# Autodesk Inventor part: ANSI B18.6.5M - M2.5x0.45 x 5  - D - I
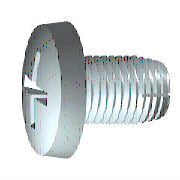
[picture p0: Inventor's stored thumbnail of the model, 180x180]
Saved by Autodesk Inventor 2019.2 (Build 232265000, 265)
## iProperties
IsCustomPart: 1
Created: 2018-01
Part Number: ANSI B18.6.5M - M2.5x0.45 x 5  - D - I
Material: Steel, Mild
Description: Cross Recessed Pan Head Tapping Screw - Type D - Type I - Metric
Document SubType Name: Modeling
Standard: ANSI B18.6.5M
Designer: richard.girt
Standard Revision: 2000 (R2010)
Standards Organization: ANSI
Language: en-US
Size Designation: M2.5x0.45 x 5
Categories: <MemberInstance><Categories><Category DisplayName="Fasteners" InternalName="e4da775c-781d-43d5-af7c-5136215cf5a6" Mnemonic="FSTN"><Category DisplayName="Bolts"
Mass: 0.411512 g
Surface Area: 1.02421 cm^2
Volume: 0.0524219 cm^3
Density: 7.85 g/cm^3
Appearance: Semi-Polished
Author: richard.girt
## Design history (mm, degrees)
revolve "Body" stored, may be unused: angle "d18" = 90 deg
node "IDS_WORKPLANE{1}"
sketch "Sketch2"
  geometry: L1 (-3.339, 0)-(3.339, 0) reference; L2 (0, -3.339)-(0, 3.339) reference; L3 (0, 1.34)-(0, 0); L4 (0, 0)-(1.34, 0); L5 (0, 0)-(1.687, 1.687); L6 (0.35, 1.293)-(0.219, 0.633); L7 (1.293, 0.35)-(0.633, 0.219); L8 (0.35, -1.293)-(0.219, -0.633); L9 (1.293, -0.35)-(0.633, -0.219); L10 (-0.35, 1.293)-(-0.219, 0.633); L11 (-1.293, 0.35)-(-0.633, 0.219); L12 (-1.293, -0.35)-(-0.633, -0.219); L13 (-0.35, -1.293)-(-0.219, -0.633); A1 r 0.447 centre (0, 0) between (0.447, 0) and (0, 0.447); A2 r 1.34 centre (0, 0) between (1.34, 0) and (1.293, 0.35); A3 r 1.34 centre (0, 0) between (0.35, 1.293) and (0, 1.34); A4 r 1.34 centre (0, 0) between (1.293, 0.35) and (0.35, 1.293); A5 r 1.34 centre (0, 0) between (0, -1.34) and (0.35, -1.293); A6 r 1.34 centre (0, 0) between (0.35, -1.293) and (1.293, -0.35); A7 r 1.34 centre (0, 0) between (1.293, -0.35) and (1.34, 0); A8 r 1.34 centre (0, 0) between (-1.293, 0.35) and (-1.34, 0); A9 r 1.34 centre (0, 0) between (-0.35, 1.293) and (-1.293, 0.35); A10 r 1.34 centre (0, 0) between (0, 1.34) and (-0.35, 1.293); A11 r 1.34 centre (0, 0) between (-1.34, 0) and (-1.293, -0.35); A12 r 1.34 centre (0, 0) between (-1.293, -0.35) and (-0.35, -1.293); A13 r 1.34 centre (0, 0) between (-0.35, -1.293) and (0, -1.34); A14 r 0.67 centre (0, 0) between (0.67, 0) and (0, 0.67); A15 r 0.352 centre (0.565, 0.565) between (0.219, 0.633) and (0.633, 0.219); A16 r 0.352 centre (0.565, -0.565) between (0.633, -0.219) and (0.219, -0.633); A17 r 0.352 centre (-0.565, 0.565) between (-0.633, 0.219) and (-0.219, 0.633); A18 r 0.352 centre (-0.565, -0.565) between (-0.219, -0.633) and (-0.633, -0.219); 1 further point
  constraints: 38 point on circle, 22 end point, 19 symmetric about line, 18 centre point, 4 coincident, 3 collinear, 3 tangent, 2 point on line, 1 midpoint, 1 perpendicular, 21 other
  dimensions: "d4" = 45 deg angle of L5 L4; "d5" = 0.89333 diameter of A1 (= 0.333333 x SDM); "d6" = 2.68 diameter of A4 (= SDM); "d7" = 0.35 distance from line of L6.start L3 (= 0.5 x SBR); "d14" = 1.34 diameter of A14 (= 0.5 x SDM)
extrude "Slot" join sketch "Sketch2" taper "d15" = 5 deg; stored distance "d54" = 10
revolve "Cut" stored, may be unused: angle "d56" = 90 deg
workplane "Work Plane3"
body "Solid1"
sketch "Sketch1"
  geometry: L1 (5, 0)-(5, 1.25); L2 (5, 1.25)-(0, 1.25); L3 (3.962, 5.08)-(3.962, 5.08); L4 (-2.1, 0)-(-2.1, 2.316); L5 (-1.902, 1.242)-(-0.988, 0.785); L6 (-0.988, 0.785)-(-0.57, 0); L7 (-0.57, 0)-(5, 0); L8 (-3.751, 0)-(6.458, 0) reference; L9 (0, -1.016)-(0, 6.096) reference; L10 (-1.902, 1.242)-(-2.1, 1.34); L11 (-1.311, 2.385)-(-2.1, 2.316); L12 (-1.311, 2.385)-(0, 2.5); L13 (0, 2.5)-(0, 1.25); A1 r 4 centre (1.9, 0) between (-1.311, 2.385) and (-2.1, 0)
  constraints: 22 end point, 4 collinear, 4 point on circle, 3 point on line, 2 parallel, 1 centre point, 1 horizontal, 1 perpendicular, 1 tangent
  dimensions: "d1" = 2.5 diameter of L2 L7 (= NND); "d2" = 1.53 distance from line of L6.end L4 (= STI); "d11" = 2.68 diameter of L10.end L7 (= SDM); "d12" = 62 deg angle of L6 L7; "d13" = 26.5 deg angle of L5 L7; "d17" = 5 diameter of L12.end L7 (= KOD); "d19" = 5 deg angle of L12 L7; "d20" = 2.1 distance between parallel lines of L4 L13 (= KOH); "d21" = 4 radius of A1 (= KR); "d23" = 5 distance between parallel lines of L1 L13 (= NLG)
fillet "Fillet1" dims "d16" = 0.14 (= 0.2 x SBR)
feature "Thread" dims "d8" = 5 (= GEL), "d9" = 0
chamfer "Chamfer1" distance "d24" = 0.31 (= -0.5 x GD2 + 0.5 x NND); stored, may be unused: second distance "d25" = 2 (= SPTZ), angle "d74" = 45 deg
other parameters: "NND" = 2.5 [user parameter; used in 2 equation terms], "NLG" = 5 [user parameter; used in 1 equation term], "GEL" = 5 [user parameter; used in 1 equation term], "KOD" = 5 [user parameter; used in 1 equation term], "KOH" = 2.1 [user parameter; used in 2 equation terms], "SDM" = 2.68 [user parameter; used in 4 equation terms], "STI" = 1.53 [user parameter; used in 1 equation term], "SBR" = 0.7 [user parameter; used in 2 equation terms], "d3" = -2.1 (= -KOH), "d10" = 0, "KR" = 4 [user parameter; used in 1 equation term], "SPTZ" = 2 [user parameter; used in 1 equation term], "GD2" = 1.88 [user parameter; used in 1 equation term], "d75" = 0, "d76" = 0, "GUL" = 0.27605 (= 0.61345 x PTC) [user parameter], "THREADDIA" = 2.5 [user parameter; used in 1 equation term], "TOA" = 30 deg [user parameter], "TPU" = 22.22222 (computed from PTC) [user parameter], "PTC" = 0.45 [user parameter; used in 4 equation terms], "GAL" = 0.27605 (= 0.61345 x PTC) [user parameter], "GD1" = 1.94789 (= THREADDIA - 1.2269 x PTC) [user parameter]
